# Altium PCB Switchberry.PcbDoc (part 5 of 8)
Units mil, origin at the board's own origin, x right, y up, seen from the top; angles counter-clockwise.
Board outline 4500 x 3824.8 mil, 6 copper layers (L01-TOP, L02-GND, L03-SIG, L04-SIG, L05-GND, L06-BOT), stack 49.214 mil thick; 431 components, 322 nets, 1699 pads, 1274 vias.
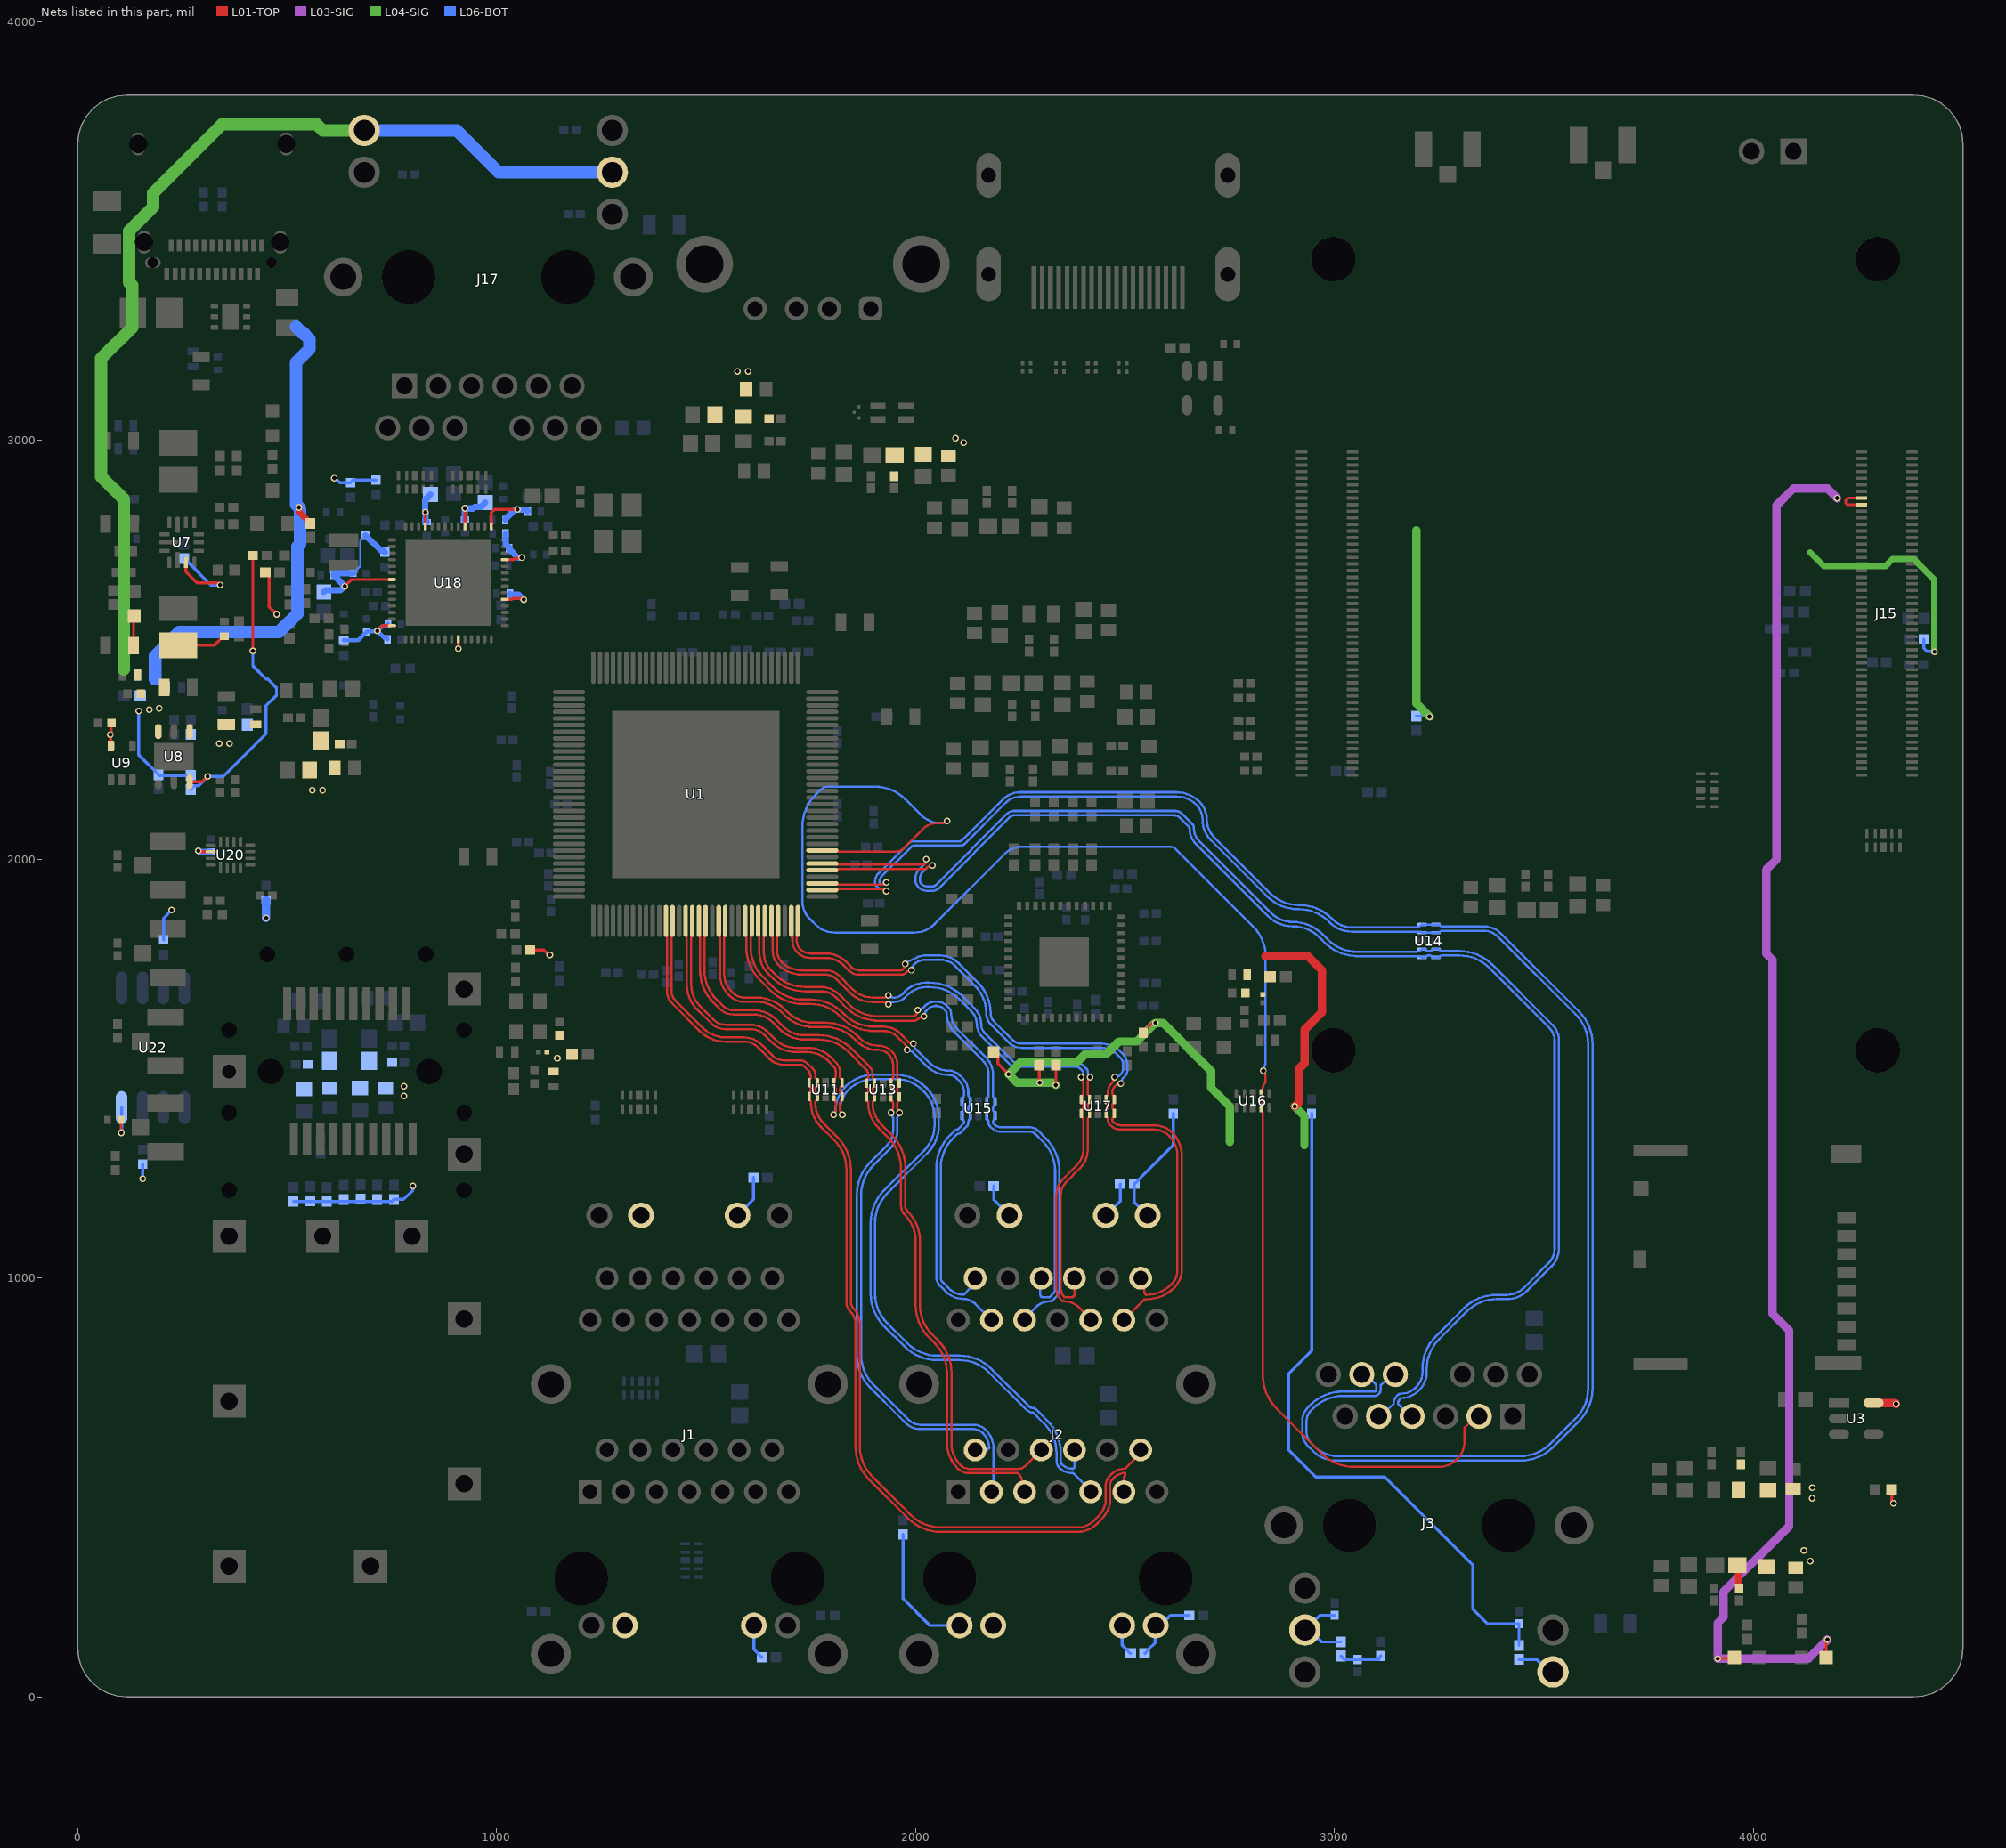
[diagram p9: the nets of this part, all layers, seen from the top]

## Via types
v1: diameter 16, hole 10, L01-TOP to L06-BOT, tented both sides, 1262 vias
v2: diameter 11.81, hole 7.87, L01-TOP to L06-BOT, tented both sides, 4 vias
v3: diameter 19.68, hole 7.87, L01-TOP to L06-BOT, tented both sides, 4 vias
v4: diameter 157.48, hole 110.24, L01-TOP to L06-BOT, tented both sides, 4 vias

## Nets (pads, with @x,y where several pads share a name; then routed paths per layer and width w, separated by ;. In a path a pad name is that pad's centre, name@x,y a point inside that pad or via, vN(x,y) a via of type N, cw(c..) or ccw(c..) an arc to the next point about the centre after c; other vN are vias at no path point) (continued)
P2_LED1: J2.34 R34.2 R98.1 | length 295.8
  L06-BOT w7.27: J2.34@2554,1150 2521.73,1182.27 R98.1@2521.73,1225 2522.72,1225 2530.89,1233.18 2530.89,1234.16 2615,1318.27 R34.2@2615,1393.27
P2_TXRXA_N: J2.13 U1.13 U11.2 U11.9 | length 2401.1
  L01-TOP w5.38: U1.13@1419.88,1852.82 1419.88,1820.14 cw(c1415.3,1820.14) 1418.54,1816.9 ccw(c1421.78,1813.66) 1417.2,1813.66 1417.2,1685 ccw(c1446.64,1685) 1425.82,1664.18 1493.79,1596.21 ccw(c1545,1647.43) 1545,1575 1589.84,1575 cw(c1589.84,1515.03) 1632.24,1557.44 1658.84,1530.84 ccw(c1685,1556.99) 1685,1520 1723.88,1520 cw(c1723.88,1493.93) 1742.31,1512.36 1754.84,1499.84 cw(c1741.66,1486.66) 1760.3,1486.66 1760.3,1482.19 ccw(c1768.86,1482.19) 1762.81,1476.13 cw(c1756.75,1470.07) 1765.31,1470.07 U11.9@1765.31,1466.44 1765.31,1460.13 cw(c1763.18,1460.13) 1764.69,1458.63 1764.07,1458 1763.81,1458 ccw(c1771.42,1450.4) 1760.66,1450.4 1760.66,1447.37 ccw(c1766.04,1447.37) 1762.24,1443.57 1763.81,1442 1764.07,1442 cw(c1761.05,1438.98) 1765.31,1438.98 U11.2@1765.31,1433.56 1765.31,1427.26 cw(c1763.18,1427.26) 1764.69,1425.75 1764.07,1425.13 1763.81,1425.13 ccw(c1771.42,1417.52) 1760.66,1417.52 ccw(c1828.71,1417.52) 1780.59,1369.41 1813.12,1336.88 cw(c1735.24,1259) 1845.38,1259 1845.38,942.75 ccw(c1866.09,942.75) 1851.45,928.1 cw(c1814.38,891.03) 1866.8,891.03 1866.8,597.99 ccw(c1966.8,597.99) 1896.09,527.28 1969.92,453.44 ; 1970,453.37 1989.08,434.29 ccw(c2059.79,505) 2059.79,405 2387.06,405 ccw(c2387.06,459.04) 2425.27,420.83 2436.23,431.8 ccw(c2393.48,474.55) 2453.94,474.55 2453.94,506.29 cw(c2483.71,506.29) 2462.66,527.34 2467.06,531.73 cw(c2500,498.79) 2500,545.38 2531.61,576.99 ccw(c2518.6,590) J2.13@2537,590
P2_TXRXA_P: J2.6 U1.12 U11.1 U11.10 | length 2403.6
  L01-TOP w5.38: U1.12@1404.13,1852.82 1404.13,1820.14 ccw(c1408.72,1820.14) 1405.48,1816.9 cw(c1402.24,1813.66) 1406.82,1813.66 1406.82,1684.97 ccw(c1446.58,1684.97) 1418.46,1656.86 1486.5,1588.82 ccw(c1544.92,1647.24) 1544.92,1564.62 1589.7,1564.62 cw(c1589.7,1514.7) 1625,1550 1651.52,1523.48 ccw(c1684.97,1556.93) 1684.97,1509.62 1723.84,1509.62 cw(c1723.84,1493.84) 1735,1505 1744.74,1495.26 cw(c1738.07,1488.59) 1747.5,1488.59 1747.5,1488.11 ccw(c1755.76,1488.11) 1749.92,1482.26 1749.92,1480.84 cw(c1742.6,1480.84) 1747.77,1475.66 ccw(c1752.95,1470.49) 1745.63,1470.49 U11.10@1745.63,1466.44 1745.63,1460.13 ccw(c1747.76,1460.13) 1746.25,1458.63 1746.88,1458 1747.13,1458 cw(c1739.53,1450.4) 1750.28,1450.4 1750.28,1447.37 cw(c1744.91,1447.37) 1748.71,1443.57 1747.13,1442 1746.88,1442 ccw(c1749.89,1438.98) 1745.63,1438.98 U11.1@1745.63,1433.56 1745.63,1427.26 ccw(c1747.76,1427.26) 1746.25,1425.75 1746.88,1425.13 1747.13,1425.13 cw(c1739.53,1417.52) 1750.28,1417.52 1750.28,1417.45 ccw(c1828.52,1417.45) 1773.2,1362.12 1805.71,1329.61 cw(c1735,1258.9) 1835,1258.9 1835,1129.96 1835,942.75 ccw(c1866.09,942.75) 1844.11,920.76 cw(c1814.38,891.03) 1856.42,891.03 1856.42,597.99 ccw(c1966.8,597.99) 1888.75,519.94 1981.74,426.95 ccw(c2059.79,505) 2059.79,394.62 2387.06,394.62 ccw(c2387.06,459.04) 2432.6,413.49 2443.57,424.46 ccw(c2393.48,474.55) 2464.32,474.55 2464.32,506.29 cw(c2483.71,506.29) 2470,520 2474.39,524.39 cw(c2500,498.79) 2500,535 2500,530.53 cw(c2494.88,530.53) 2498.5,526.91 ccw(c2502.12,523.29) 2497,523.29 J2.6@2497,490
P2_TXRXB_N: J2.5 U1.16 U11.5 U11.6 | length 2282.6
  L01-TOP w5.38: U1.16@1467.13,1852.82 1467.13,1820.14 cw(c1462.54,1820.14) 1465.78,1816.9 ccw(c1469.02,1813.66) 1464.44,1813.66 1464.44,1699.63 ccw(c1534.63,1699.63) 1484.97,1650.03 1519.44,1615.56 ccw(c1544.94,1641.07) 1544.94,1605 1604.84,1605 cw(c1604.84,1545.03) 1647.24,1587.44 1663.23,1571.44 ccw(c1715,1623.21) 1715,1550 1742.66,1550 cw(c1742.66,1472.72) 1797.31,1527.36 1810.19,1514.48 cw(c1787.2,1491.49) 1819.72,1491.49 1819.72,1480.25 ccw(c1825.09,1480.25) 1821.29,1476.45 1822.87,1474.87 1823.12,1474.87 cw(c1820.11,1471.86) U11.6@1824.37,1471.86 ; U11.6@1824.37,1466.44 1824.37,1460.13 cw(c1822.24,1460.13) 1823.75,1458.63 1823.12,1458 1822.87,1458 ccw(c1830.47,1450.4) 1819.72,1450.4 1819.72,1447.37 ccw(c1825.09,1447.37) 1821.29,1443.57 1822.87,1442 1823.12,1442 cw(c1820.11,1438.98) 1824.37,1438.98 U11.5@1824.37,1433.56 1824.37,1427.26 cw(c1822.24,1427.26) 1823.75,1425.75 1823.12,1425.13 1822.87,1425.13 ccw(c1830.47,1417.52) 1819.72,1417.52 1819.72,1401.94 ccw(c1828.78,1401.94) 1822.37,1395.53 1823,1394.91 cw(c1818.09,1390) v1(1825.03,1390)
  L06-BOT w5.38: v1(1825.03,1390) ccw(c1818.09,1390) 1823,1394.91 cw(c1830.91,1402.82) 1819.72,1402.82 cw(c1884.36,1402.82) 1838.65,1448.53 1840.12,1450 cw(c1900.47,1389.64) 1900.47,1475 1954.75,1475 1954.82,1475 cw(c1954.82,1390.07) 2014.93,1450.07 2020.36,1444.64 cw(c1960.62,1385.05) 2045,1385.48 cw(c1940.61,1385) 2045,1385 2045,1365.29 cw(c1959.97,1365.22) 2020.06,1305.06 1925.08,1210.08 ccw(c2003.13,1132.04) 1892.76,1132.04 1892.76,963.29 ccw(c2003.13,963.29) 1925.08,885.24 1973.37,836.95 ccw(c2051.42,915) 2051.42,804.62 2105,804.62 cw(c2105,707.14) 2173.93,776.07 2263.57,686.43 ccw(c2280,702.85) 2280,679.62 2306.89,652.73 cw(c2236.18,582.02) 2336.18,582.02 2336.18,563.3 ccw(c2358.3,563.3) 2342.66,547.66 ccw(c2374.14,579.14) 2374.14,534.62 cw(c2374.14,530.5) 2377.06,533.41 2416.25,494.22 cw(c2412.03,490) J2.5@2418,490
P2_TXRXB_P: J2.11 U1.15 U11.4 U11.7 | length 2287.8
  L01-TOP w5.38: U1.15@1451.38,1852.82 1451.38,1820.14 ccw(c1455.96,1820.14) 1452.72,1816.9 cw(c1449.48,1813.66) 1454.06,1813.66 1454.06,1699.59 ccw(c1534.52,1699.59) 1477.63,1642.69 1512.1,1608.23 ccw(c1544.94,1641.07) 1544.94,1594.62 1604.77,1594.62 ; 1604.81,1594.62 cw(c1604.84,1545.03) 1639.91,1580.09 1639.96,1580.04 1655.92,1564.08 ccw(c1714.97,1623.14) 1714.97,1539.62 1742.63,1539.62 cw(c1742.63,1446.36) 1742.85,1539.62 cw(c1742.66,1472.72) 1790.02,1519.98 1802.9,1507.1 cw(c1782.66,1486.98) 1802.97,1507.02 cw(c1787.2,1491.49) 1809.34,1491.49 1809.34,1484.44 1806.47,1468.22 1805.93,1467.69 U11.7@1804.68,1466.44 1804.68,1460.13 ccw(c1806.82,1460.13) 1805.31,1458.63 1805.93,1458 1806.19,1458 cw(c1798.58,1450.4) 1809.34,1450.4 1809.34,1447.37 cw(c1803.96,1447.37) 1807.76,1443.57 1806.19,1442 1805.93,1442 ccw(c1808.95,1438.98) 1804.68,1438.98 U11.4@1804.68,1433.56 1804.68,1427.26 ccw(c1806.82,1427.26) 1805.31,1425.75 1805.93,1425.13 1806.19,1425.13 cw(c1798.58,1417.52) 1809.34,1417.52 1809.34,1401.94 cw(c1800.27,1401.94) 1806.68,1395.53 1806.06,1394.91 ccw(c1810.97,1390) v1(1804.03,1390)
  L06-BOT w5.38: v1(1804.03,1390) cw(c1810.97,1390) 1806.06,1394.91 ccw(c1798.14,1402.82) 1809.34,1402.82 ; 1809.34,1402.87 cw(c1884.25,1402.87) 1831.28,1455.84 1832.8,1457.36 cw(c1900.45,1389.71) 1900.45,1485.38 1954.82,1485.38 cw(c1954.82,1390.07) 2022.21,1457.46 2027.63,1452.05 cw(c1960.62,1385.05) 2055.38,1385.05 2055.38,1365.22 cw(c1959.97,1365.22) 2027.43,1297.76 1932.42,1202.75 ccw(c2003.13,1132.04) 1903.13,1132.04 1903.13,963.29 ccw(c2003.13,963.29) 1932.42,892.58 1980.71,844.29 ccw(c2051.42,915) 2051.42,815 2105,815 cw(c2105,707.14) 2181.27,783.41 2270.91,693.76 ccw(c2280,702.85) 2280,690 cw(c2280,679.62) 2287.34,686.96 2314.23,660.07 cw(c2236.18,582.02) 2346.56,582.02 2346.56,563.3 ccw(c2358.3,563.3) 2350,555 ccw(c2374.14,579.14) 2374.14,545 ccw(c2374.14,549.12) 2377.06,546.21 ccw(c2372.37,550.9) 2379,550.9 J2.11@2379,590
P2_TXRXC_N: J2.10 U1.18 U13.2 U13.9 | length 1849
  L01-TOP w5.38: U1.18@1498.62,1852.82 1498.62,1820.14 cw(c1494.04,1820.14) 1497.28,1816.9 ccw(c1500.52,1813.66) 1495.94,1813.66 1495.94,1735.16 ccw(c1595.16,1735.16) 1525,1665 1539.39,1650.61 ccw(c1565,1676.21) 1565,1640 1612.66,1640 cw(c1612.66,1562.72) 1667.31,1617.36 1683.23,1601.44 ccw(c1735,1653.21) 1735,1580 1769.06,1580 cw(c1769.06,1469.86) 1846.93,1547.74 1890.58,1504.1 cw(c1873.86,1487.38) 1897.51,1487.38 1897.51,1479.81 ccw(c1902.88,1479.81) 1899.08,1476.01 1900.66,1474.43 1900.91,1474.43 cw(c1897.9,1471.42) 1902.16,1471.42 U13.9@1902.16,1466 1902.16,1459.7 cw(c1900.03,1459.7) 1901.54,1458.19 1900.91,1457.57 1900.66,1457.57 ccw(c1908.26,1449.96) 1897.51,1449.96 1897.51,1446.94 ccw(c1902.88,1446.94) 1899.08,1443.13 1900.66,1441.56 1900.91,1441.56 cw(c1897.9,1438.55) 1902.16,1438.55 U13.2@1902.16,1433.13 1902.16,1426.82 cw(c1900.03,1426.82) 1901.54,1425.32 1900.91,1424.69 1900.66,1424.69 ccw(c1908.26,1417.09) 1897.51,1417.09 ccw(c1968.95,1417.09) 1918.43,1366.57 1943.12,1341.88 cw(c1865.24,1264) 1975.38,1264 1975.38,1173.58 ccw(c1997.01,1173.58) 1981.71,1158.29 cw(c1912.51,1089.08) 2010.38,1089.08 2010.38,936.04 ccw(c2110.38,936.04) 2039.67,865.33 2053.05,851.95 cw(c1975,773.9) 2085.38,773.9 2085.38,606.37 ccw(c2160.34,606.37) 2107.33,553.36 ccw(c2127.92,573.94) 2127.92,544.84 2245,544.84 ccw(c2245,568.58) 2261.79,551.79 J2.10@2300,590
P2_TXRXC_P: J2.3 U1.17 U13.1 U13.10 | length 1840.9
  L01-TOP w5.38: U1.17@1482.87,1852.82 1482.87,1820.14 ccw(c1487.46,1820.14) 1484.22,1816.9 cw(c1480.98,1813.66) 1485.56,1813.66 1485.56,1735.1 ccw(c1595.01,1735.1) 1517.62,1657.71 1532.1,1643.23 ccw(c1564.94,1676.07) 1564.94,1629.62 1612.63,1629.62 cw(c1612.63,1562.63) 1660,1610 1675.92,1594.08 ccw(c1734.97,1653.14) 1734.97,1569.62 1768.96,1569.62 cw(c1768.96,1469.62) 1839.67,1540.33 1881.72,1498.28 cw(c1868.67,1485.23) 1887.13,1485.23 1887.13,1479.81 cw(c1881.75,1479.81) 1885.55,1476.01 1883.98,1474.43 1883.72,1474.43 ccw(c1886.74,1471.42) 1882.47,1471.42 U13.10@1882.47,1466 1882.47,1459.7 ccw(c1884.6,1459.7) 1883.1,1458.19 1883.72,1457.57 1883.98,1457.57 cw(c1876.37,1449.96) 1887.13,1449.96 1887.13,1446.94 cw(c1881.75,1446.94) 1885.55,1443.13 1883.98,1441.56 1883.72,1441.56 ccw(c1886.74,1438.55) 1882.47,1438.55 U13.1@1882.47,1433.13 1882.47,1426.82 ccw(c1884.6,1426.82) 1883.1,1425.32 1883.72,1424.69 1883.98,1424.69 cw(c1876.37,1417.09) 1887.13,1417.09 ; 1887.13,1417.04 ccw(c1968.84,1417.04) 1911.06,1359.26 1935.71,1334.61 cw(c1865,1263.9) 1965,1263.9 1965,1173.58 ccw(c1997.01,1173.58) 1974.37,1150.95 cw(c1912.51,1089.08) 2000,1089.08 2000,936.04 ccw(c2110.38,936.04) 2032.33,857.99 2045.71,844.61 cw(c1975,773.9) 2075,773.9 2075,606.37 ccw(c2160.34,606.37) 2100,546.02 ccw(c2127.92,573.94) 2127.92,534.46 2245,534.46 cw(c2223.15,512.61) 2254.05,512.61 2254.05,504.37 ccw(c2274.37,504.37) J2.3@2260,490
P2_TXRXD_N: J2.2 U1.21 U13.5 U13.6 | length 1905.5
  L01-TOP w5.38: U1.21@1545.87,1852.82 1545.87,1820.14 cw(c1541.28,1820.14) 1544.52,1816.9 ccw(c1547.76,1813.66) 1543.18,1813.66 1543.18,1725.84 ccw(c1600.6,1725.84) 1560,1685.23 1564.79,1680.44 ccw(c1590,1705.65) 1590,1670 1620.59,1670 cw(c1620.59,1575.65) 1687.31,1642.36 1694.7,1634.98 ccw(c1755,1695.28) 1755,1610 1784.06,1610 cw(c1784.06,1499.86) 1861.93,1577.74 1866.13,1573.55 ccw(c1910,1617.43) 1866.18,1573.5 ccw(c1910,1617.43) 1910,1555.38 1910.98,1555.38 cw(c1910.98,1511.15) 1942.25,1542.42 1942.42,1542.25 cw(c1908.29,1508.12) 1956.56,1508.12 1956.56,1479.81 ccw(c1961.94,1479.81) 1958.14,1476.01 1959.71,1474.43 1959.97,1474.43 cw(c1956.95,1471.42) 1961.21,1471.42 U13.6@1961.21,1466 1961.21,1459.7 cw(c1959.08,1459.7) 1960.59,1458.19 1959.97,1457.57 1959.71,1457.57 ccw(c1967.32,1449.96) 1956.56,1449.96 1956.56,1446.94 ccw(c1961.94,1446.94) 1958.14,1443.13 1959.71,1441.56 1959.97,1441.56 cw(c1956.95,1438.55) 1961.21,1438.55 U13.5@1961.21,1433.13 1961.21,1426.82 cw(c1959.08,1426.82) 1960.59,1425.32 1959.97,1424.69 1959.71,1424.69 ccw(c1967.32,1417.09) 1956.56,1417.09 1956.56,1406.94 ccw(c1965.63,1406.94) 1959.22,1400.53 1959.84,1399.91 cw(c1954.93,1395) v1(1961.87,1395)
  L06-BOT w5.38: v1(1961.87,1395) cw(c1954.93,1395) 1959.84,1390.09 ccw(c1967.75,1382.18) 1956.56,1382.18 1956.56,1353.96 cw(c1891.18,1353.96) 1937.41,1307.74 1899.29,1269.61 ccw(c1970,1198.9) 1870,1198.9 1870,816.42 ccw(c1970,816.42) 1899.29,745.71 1982.5,662.5 ccw(c2012.68,692.68) 2012.68,650 2138.64,650 cw(c2138.64,610.39) 2166.65,638.4 2168.4,636.65 cw(c2125.79,594.04) 2186.05,594.04 cw(c2175.67,594.04) 2186.04,593.81 2185.98,590.77 ccw(c2221,590) 2186.04,587.84 cw(c2180.67,587.49) 2186.05,587.49 2186.05,502.18 cw(c2168.82,502.18) J2.2@2181,490
P2_TXRXD_P: J2.8 U1.20 U13.4 U13.7 | length 1834.9
  L01-TOP w5.38: U1.20@1530.12,1852.82 1530.12,1820.14 ccw(c1534.7,1820.14) 1531.46,1816.9 cw(c1528.22,1813.66) 1532.8,1813.66 1532.8,1725.79 ccw(c1600.49,1725.79) 1552.63,1677.93 1557.51,1673.05 ccw(c1589.92,1705.47) 1589.92,1659.62 1620.56,1659.62 cw(c1620.56,1575.56) 1680,1635 1687.38,1627.62 ccw(c1754.97,1695.21) 1754.97,1599.62 1783.96,1599.62 cw(c1783.96,1499.62) 1854.62,1570.38 1861.83,1563.17 1865.21,1560.51 ccw(c1910,1617.43) 1901.43,1545.51 1905.7,1545 1910.86,1545 ; 1910.9,1545 cw(c1910.86,1510.86) 1935,1535 cw(c1908,1508) 1946.18,1508 1946.18,1479.81 cw(c1940.8,1479.81) 1944.61,1476.01 1943.03,1474.43 1942.78,1474.43 ccw(c1945.79,1471.42) 1941.53,1471.42 U13.7@1941.53,1466 1941.53,1459.7 ccw(c1943.66,1459.7) 1942.15,1458.19 1942.78,1457.57 1943.03,1457.57 cw(c1935.43,1449.96) 1946.18,1449.96 1946.18,1446.94 cw(c1940.8,1446.94) 1944.61,1443.13 1943.03,1441.56 1942.78,1441.56 ccw(c1945.79,1438.55) 1941.53,1438.55 U13.4@1941.53,1433.13 1941.53,1426.82 ccw(c1943.66,1426.82) 1942.15,1425.32 1942.78,1424.69 1943.03,1424.69 cw(c1935.43,1417.09) 1946.18,1417.09 1946.18,1406.94 cw(c1937.12,1406.94) 1943.53,1400.53 1942.9,1399.91 ccw(c1947.81,1395) v1(1940.87,1395)
  L06-BOT w5.38: v1(1940.87,1395) ccw(c1947.81,1395) 1942.9,1390.09 cw(c1934.99,1382.18) 1946.18,1382.18 1946.18,1354.07 cw(c1890.93,1354.07) 1930,1315 1891.92,1276.92 ccw(c1969.89,1198.95) 1859.62,1198.95 1859.62,816.42 ccw(c1970,816.42) 1891.95,738.37 1962.66,667.66 1975.16,655.16 ccw(c2012.68,692.68) 2012.68,639.62 2138.64,639.62 cw(c2138.64,610.39) 2159.31,631.06 2161.06,629.31 cw(c2125.79,594.04) 2175.67,594.04 cw(c2168.06,601.65) 2168.06,590.89 2144.15,590.89 ccw(c2144.15,587.85) J2.8@2142,590
P2V5: C56.1 C57.1 C58.1 C59.2 C106.1 C107.2 C108.1 C149.1 C150.2 C151.1 FB8.1 FB10.1 R72.2 U8.4
  other v1: 560,2165 585,2165 337.84,2276.55 362.84,2276.55 2115,2995 2095,3005
P2V5_PGOOD: R71.1 R79.2 U8.3 | length 745
  L01-TOP w7.27: U8.3@267.4,2184.96 296.76,2184.96 309.54,2197.75 v1(310.71,2197.75) ; v1(418.27,2497.12) R79.2@418.27,2725
  L06-BOT w7.27: R71.1@270,2166.54 270,2167.52 278.18,2175.7 288.66,2175.7 v1(310.71,2197.75) 347.75,2197.75 450,2300 450,2366.42 474.57,2390.98 474.57,2408.96 453.53,2430 450,2430 418.27,2461.73 v1(418.27,2497.12)
P3_LED0: J2.27 R35.2 | length 314.8
  L06-BOT w7.27: R35.2@1970,388.27 1970,235 2034,171 J2.27@2105,171
P3_LED1: J2.30 R36.2 R102.1 | length 167.7
  L06-BOT w7.27: R102.1@2546.73,105 2547.72,105 2555.89,113.18 2555.89,114.16 2571,129.27 2571,169 J2.30@2573,171 2584.02,171 2608.02,195 R36.2@2653.27,195
P3_TXRXA_N: J2.21 U1.25 U15.2 U15.9 | length 1334.2
  L01-TOP w5.38: U1.25@1608.86,1852.82 1608.86,1820.14 cw(c1604.27,1820.14) 1607.52,1816.9 ccw(c1610.76,1813.66) 1606.17,1813.66 1606.17,1790.25 ccw(c1706.17,1790.25) 1635.46,1719.54 1660.71,1694.29 ccw(c1731.42,1765) 1731.42,1665 1750.03,1665 cw(c1750.03,1557.21) 1826.25,1633.43 1830.01,1629.67 ccw(c1900.72,1700.38) 1900.72,1600.38 1923.96,1600.38 cw(c1923.96,1545.2) 1962.97,1584.22 1982.65,1564.54 ccw(c1989.06,1570.95) 1989.06,1561.88 1989.94,1561.88 cw(c1989.94,1554.94) v1(1994.85,1559.85)
  L06-BOT w5.38: v1(1994.85,1559.85) cw(c1989.94,1554.94) 1996.88,1554.94 1996.88,1554.06 ccw(c2005.95,1554.06) 1999.54,1547.65 2031.88,1515.31 ; 2031.89,1515.3 ccw(c2080,1563.44) 2080,1495.38 cw(c2080.03,1460.93) 2104.39,1485.29 2112.37,1477.31 cw(c2080.29,1445.22) 2125.66,1445.22 2125.66,1437.48 ccw(c2136.42,1437.48) 2128.81,1429.87 2129.07,1429.87 2129.69,1429.25 cw(c2128.18,1427.74) 2130.31,1427.74 U15.2@2130.31,1421.44 2130.31,1415.13 cw(c2128.18,1415.13) 2129.69,1413.63 2129.07,1413 2128.81,1413 ccw(c2136.42,1405.4) 2125.66,1405.4 2125.66,1402.37 ccw(c2131.04,1402.37) 2127.24,1398.57 2128.81,1397 2129.07,1397 cw(c2126.05,1393.98) 2130.31,1393.98 U15.9@2130.31,1388.56 2130.31,1382.26 cw(c2128.18,1382.26) 2129.69,1380.75 2129.07,1380.13 2128.81,1380.13 ccw(c2136.42,1372.52) 2125.66,1372.52 2125.66,1369.99 cw(c2115.31,1369.99) 2122.63,1362.67 2107.59,1347.63 cw(c2100.32,1354.9) 2100.32,1344.62 2100,1344.62 2089.29,1333.91 ccw(c2160,1263.2) 2060,1263.2 2060,1002.07 ccw(c2077.07,1002.07) 2065,990 2079.62,975.38 ccw(c2114.84,1010.61) 2114.84,960.79 2133.48,979.43 ccw(c2112.9,1000) J2.21@2142,1000
P3_TXRXA_P: J2.15 U1.24 U15.1 U15.10 | length 1386.7
  L01-TOP w5.38: U1.24@1593.11,1852.82 1593.11,1820.14 ccw(c1597.69,1820.14) 1594.45,1816.9 cw(c1591.21,1813.66) 1595.8,1813.66 1595.8,1790.22 ccw(c1706.11,1790.22) 1628.11,1712.22 1653.39,1686.93 ccw(c1731.39,1764.93) 1731.39,1654.62 1750,1654.62 cw(c1750,1557.14) 1818.93,1626.07 1822.69,1622.31 ccw(c1900.69,1700.31) 1900.69,1590 1923.87,1590 cw(c1923.87,1544.99) 1955.69,1576.82 1975.31,1557.2 cw(c1968.9,1550.79) 1977.97,1550.79 1977.97,1549.91 ccw(c1984.91,1549.91) v1(1980,1545)
  L06-BOT w5.38: v1(1980,1545) ccw(c1984.91,1549.91) 1984.91,1542.97 1985.79,1542.97 cw(c1985.79,1533.9) 1992.2,1540.31 2024.54,1507.97 ; 2024.56,1507.95 ccw(c2080,1563.44) 2080,1485 cw(c2080,1460.86) 2097.07,1477.93 2105,1470 cw(c2080.17,1445.17) 2115.28,1445.17 2115.28,1437.48 cw(c2104.53,1437.48) 2112.13,1429.87 2111.88,1429.87 2111.25,1429.25 ccw(c2112.76,1427.74) 2110.63,1427.74 U15.1@2110.63,1421.44 2110.63,1415.13 ccw(c2112.76,1415.13) 2111.25,1413.63 2111.88,1413 2112.13,1413 cw(c2104.53,1405.4) 2115.28,1405.4 2115.28,1402.37 cw(c2109.91,1402.37) 2113.71,1398.57 2112.13,1397 2111.88,1397 ccw(c2114.89,1393.98) 2110.63,1393.98 U15.10@2110.63,1388.56 2110.63,1382.26 ccw(c2112.76,1382.26) 2111.25,1380.75 2111.88,1380.13 2112.13,1380.13 cw(c2104.53,1372.52) 2115.28,1372.52 2115.28,1370 2100.28,1355 2099.99,1355 ccw(c2099.99,1344.65) 2092.67,1351.97 2081.92,1341.22 ccw(c2159.89,1263.25) 2049.62,1263.25 2049.62,1002.07 ccw(c2077.07,1002.07) 2057.66,982.66 2072.28,968.04 ccw(c2114.84,1010.61) 2114.84,950.41 cw(c2114.84,912.41) 2141.72,939.28 J2.15@2181,900
P3_TXRXB_N: J2.16 U1.27 U15.5 U15.6 | length 1548.2
  L01-TOP w5.38: U1.27@1640.35,1852.82 1640.35,1820.14 cw(c1635.77,1820.14) 1639.01,1816.9 ccw(c1642.25,1813.66) 1637.67,1813.66 1637.67,1776.84 ccw(c1696.84,1776.84) 1655,1735 1665.43,1724.57 ccw(c1736.14,1795.28) 1736.14,1695.28 1774.06,1695.28 cw(c1774.06,1634.12) 1817.31,1677.36 1840.39,1654.29 ccw(c1911.1,1725) 1911.1,1625 1993.65,1625 ccw(c1993.65,1634.32) 2000.24,1627.73 2000.31,1627.8 ccw(c1993.9,1634.21) 2002.97,1634.21 2002.97,1635.09 cw(c2009.91,1635.09) v1(2005,1640)
  L06-BOT w5.38: v1(2005,1640) cw(c2009.91,1635.09) 2009.91,1642.03 2010.79,1642.03 ccw(c2010.79,1651.1) 2017.2,1644.69 2023.72,1651.21 cw(c2036.82,1638.1) 2027.62,1654.19 2028.86,1654.95 cw(c2048.01,1623.87) 2039.6,1659.4 2043.71,1660.38 2052.89,1660.38 2056.98,1659.44 cw(c2048.59,1622.46) 2068.78,1654.56 2072.36,1652.31 2081.2,1643.48 2082.92,1639.64 cw(c2061.64,1630) 2083.51,1638.21 2084.99,1634.32 ; 2085,1634.3 2085,1630 ccw(c2134.06,1630) 2099.37,1595.31 2167.14,1527.54 cw(c2124.7,1485.1) 2184.72,1485.1 2184.72,1433.02 2187.87,1429.87 2188.12,1429.87 2189.37,1428.62 U15.5@2189.37,1421.44 2189.37,1415.13 cw(c2187.24,1415.13) 2188.75,1413.63 2188.12,1413 2187.87,1413 ccw(c2195.47,1405.4) 2184.72,1405.4 2184.72,1402.37 ccw(c2190.09,1402.37) 2186.29,1398.57 2187.87,1397 2188.12,1397 cw(c2185.11,1393.98) 2189.37,1393.98 U15.6@2189.37,1388.56 2189.37,1382.26 cw(c2187.24,1382.26) 2188.75,1380.75 2188.12,1380.13 2187.87,1380.13 ccw(c2195.47,1372.52) 2184.72,1372.52 2184.72,1370 2187.45,1367.27 ccw(c2205,1384.83) 2205,1360 2273.88,1360 cw(c2273.88,1333.93) 2292.31,1352.36 2310.97,1333.71 cw(c2233.09,1255.83) 2343.23,1255.83 2343.23,975 cw(c2315.59,975) 2335.13,955.46 2327.34,947.66 cw(c2320,955) 2320,944.62 ccw(c2320,898.16) 2287.15,931.01 2262.73,906.6 ccw(c2269.33,900) J2.16@2260,900
P3_TXRXB_P: J2.23 U1.26 U15.4 U15.7 | length 1519.2
  L01-TOP w5.38: U1.26@1624.61,1852.82 1624.61,1820.14 ccw(c1629.19,1820.14) 1625.95,1816.9 cw(c1622.71,1813.66) 1627.29,1813.66 1627.29,1776.79 ccw(c1696.73,1776.79) 1647.63,1727.69 1658.11,1717.21 ccw(c1736.12,1795.21) 1736.12,1684.9 1774.03,1684.9 cw(c1774.03,1634.03) 1810,1670 1836.09,1643.91 1839.36,1641.12 ccw(c1911.1,1725) 1902.51,1614.96 1906.8,1614.62 1995.8,1614.62 ccw(c1995.8,1629.13) 2006.06,1618.87 2007.65,1620.46 cw(c2014.06,1614.05) 2014.06,1623.12 2014.94,1623.12 ccw(c2014.94,1630.06) v1(2019.85,1625.15)
  L06-BOT w5.38: v1(2019.85,1625.15) ccw(c2014.94,1630.06) 2021.88,1630.06 2021.88,1630.94 cw(c2030.95,1630.94) 2024.54,1637.35 2029.53,1642.35 cw(c2048.01,1623.87) 2048.01,1650 2048.59,1650 cw(c2048.59,1622.46) 2068.07,1641.93 2070.82,1639.18 cw(c2061.64,1630) 2074.62,1630 ccw(c2134,1629.97) 2092.01,1587.99 2159.73,1520.27 cw(c2124.46,1485) 2174.34,1485 2174.34,1433.02 2171.19,1429.87 2170.93,1429.87 2169.68,1428.62 U15.4@2169.68,1421.44 2169.68,1415.13 ccw(c2171.82,1415.13) 2170.31,1413.63 2170.93,1413 2171.19,1413 cw(c2163.58,1405.4) 2174.34,1405.4 2174.34,1402.37 cw(c2168.96,1402.37) 2172.76,1398.57 2171.19,1397 2170.93,1397 ccw(c2173.95,1393.98) 2169.68,1393.98 U15.7@2169.68,1388.56 2169.68,1382.26 ccw(c2171.82,1382.26) 2170.31,1380.75 2170.93,1380.13 2171.19,1380.13 cw(c2163.58,1372.52) 2174.34,1372.52 2174.34,1369.99 ccw(c2184.69,1369.99) 2177.37,1362.67 2180.15,1359.89 ccw(c2204.94,1384.68) 2204.94,1349.62 2273.84,1349.62 cw(c2273.84,1333.84) 2285,1345 2303.56,1326.44 cw(c2232.85,1255.73) 2332.85,1255.73 2332.85,975 cw(c2315.59,975) 2327.79,962.79 2320,955 2302.98,955 cw(c2302.98,960.38) 2299.18,956.58 cw(c2302.98,960.38) 2297.61,960.38 2297.61,994.22 cw(c2305.78,994.22) J2.23@2300,1000
P3_TXRXC_N: J2.24 U1.29 U17.2 U17.9 | length 1612.5
  L01-TOP w5.38: U1.29@1671.85,1852.82 1671.85,1820.14 cw(c1667.27,1820.14) 1670.51,1816.9 ccw(c1673.75,1813.66) 1669.17,1813.66 1669.17,1781.16 ccw(c1706.16,1781.16) 1680,1755 ccw(c1728.28,1803.28) 1728.28,1735 1786.81,1735 cw(c1786.81,1691.86) 1817.31,1722.36 1849.9,1689.78 ccw(c1898.4,1738.29) 1898.4,1669.69 1923.06,1669.69 ccw(c1923.06,1678.76) 1929.47,1672.34 1930.09,1672.97 cw(c1935,1668.06) v1(1935,1675) ; J2.24@2379,1000 2379,960.38 cw(c2373.62,960.38) 2377.42,956.58 cw(c2373.62,960.38) 2373.62,955 2355,955 cw(c2375.8,975.8) 2346.39,975.8 2346.39,1197.13 cw(c2392.87,1197.13) 2360,1230 2375.64,1245.64 2375.64,1245.96 2392.41,1262.74 ccw(c2348.36,1306.79) 2410.66,1306.79 2410.66,1377.52 cw(c2421.42,1377.52) 2413.81,1385.13 2414.07,1385.13 2414.69,1385.75 ccw(c2413.18,1387.26) 2415.31,1387.26 U17.2@2415.31,1393.56 2415.31,1400.75 2414.07,1402 2413.81,1402 2410.66,1405.15 2410.66,1414.85 2413.81,1418 2414.07,1418 2415.31,1419.25 U17.9@2415.31,1426.44 2415.31,1432.74 ccw(c2413.18,1432.74) 2414.69,1434.25 2414.07,1434.87 2413.81,1434.87 cw(c2421.42,1442.48) 2410.66,1442.48 2410.66,1468.06 cw(c2419.73,1468.06) 2413.32,1474.47 2413.94,1475.09 ccw(c2409.03,1480) v1(2415.97,1480)
  L06-BOT w5.38: v1(1935,1675) cw(c1935,1668.06) 1939.91,1672.97 ccw(c1947.82,1680.88) 1947.82,1669.69 ccw(c1947.82,1698.34) 1968.08,1678.08 1975,1685 cw(c2024.2,1635.8) 2024.2,1705.38 2033.68,1705.38 cw(c2033.68,1595.24) 2111.56,1673.12 2140.55,1644.13 cw(c2101.51,1605.09) 2156.72,1605.09 2156.72,1605 ccw(c2185,1605) 2165,1585 2231.65,1518.35 ccw(c2239.73,1526.43) 2239.73,1515 2380.34,1515 cw(c2380.34,1484.73) 2401.74,1506.13 2407.47,1500.41 ; 2407.48,1500.4 cw(c2399.76,1492.7) 2410.66,1492.7 2410.66,1491.94 ccw(c2419.73,1491.94) 2413.32,1485.53 2413.94,1484.91 cw(c2409.03,1480) v1(2415.97,1480)
P3_TXRXC_P: J2.18 U1.28 U17.1 U17.10 | length 1642.8
  L01-TOP w5.38: U1.28@1656.1,1852.82 1656.1,1820.14 ccw(c1660.69,1820.14) 1657.44,1816.9 cw(c1654.2,1813.66) 1658.79,1813.66 1658.79,1781.11 ccw(c1706.04,1781.11) 1672.63,1747.69 ; 1672.66,1747.66 ccw(c1728.28,1803.28) 1728.28,1724.62 1786.77,1724.62 cw(c1786.77,1691.77) 1810,1715 1844.08,1680.92 ccw(c1896.25,1733.1) 1896.25,1659.31 1923.06,1659.31 cw(c1923.06,1650.24) 1929.47,1656.66 1930.09,1656.03 ccw(c1935,1660.94) v1(1935,1654) ; v1(2394.97,1480) ccw(c2401.91,1480) 2397,1475.1 2397.63,1474.47 cw(c2391.22,1468.06) 2400.28,1468.06 2400.28,1442.48 cw(c2389.53,1442.48) 2397.13,1434.87 2396.88,1434.87 2396.25,1434.25 ccw(c2397.76,1432.74) 2395.63,1432.74 U17.10@2395.63,1426.44 2395.63,1419.25 2396.88,1418 2397.13,1418 2400.28,1414.85 2400.28,1405.15 2397.13,1402 2396.88,1402 2395.63,1400.75 U17.1@2395.63,1393.56 2395.63,1387.26 ccw(c2397.76,1387.26) 2396.25,1385.75 2396.88,1385.13 2397.13,1385.13 cw(c2389.53,1377.52) 2400.28,1377.52 2400.28,1306.86 ; 2400.28,1306.82 cw(c2348.36,1306.79) 2385.09,1270.09 2385,1270 2365.26,1250.26 2365.26,1249.94 2352.66,1237.34 ccw(c2392.87,1197.13) 2336.01,1197.13 2336.01,975.8 ccw(c2375.8,975.8) 2347.66,947.66 ccw(c2355,955) 2355,944.62 cw(c2355,894.29) 2390.59,929.88 2416.25,904.22 cw(c2412.03,900) J2.18@2418,900
  L06-BOT w5.38: v1(1935,1654) ccw(c1935,1660.94) 1939.91,1656.03 cw(c1947.82,1648.12) 1947.82,1659.31 1947.91,1659.31 ccw(c1947.91,1698.14) 1975.36,1670.68 1981.77,1677.09 cw(c2025,1633.86) 2025,1695 2033.58,1695 cw(c2033.58,1595) 2104.29,1665.71 2133.12,1636.88 cw(c2101.51,1605.09) 2146.34,1605.09 2146.34,1600.7 ; 2146.34,1600.7 2147.28,1596.53 ccw(c2185,1605) 2152.33,1584.33 2154.62,1580.7 2217.06,1518.27 2224.27,1511.05 ; 2224.3,1511.03 ccw(c2239.73,1526.43) 2224.33,1510.99 ccw(c2239.73,1526.43) 2239.73,1504.62 2380.3,1504.62 cw(c2380.3,1484.64) 2394.43,1498.77 2398.61,1494.59 cw(c2394.57,1490.55) 2400.28,1490.55 cw(c2394.57,1490.55) 2398.61,1486.51 2397,1484.91 ccw(c2401.91,1480) v1(2394.97,1480)
P3_TXRXD_N: J2.19 U1.32 U17.5 U17.6 | length 1851.9
  L01-TOP w5.38: U1.32@1719.09,1852.82 1719.09,1820.14 cw(c1714.51,1820.14) 1717.75,1816.9 ccw(c1720.99,1813.66) 1716.41,1813.66 1716.41,1805.74 1716.41,1805.57 ccw(c1750.54,1805.74) 1716.41,1805.42 ccw(c1745.65,1805.7) 1724.99,1785.01 ccw(c1749.06,1808.94) 1749.06,1775 1786.62,1775 cw(c1786.62,1707.27) 1834.52,1755.16 1847.34,1742.34 ccw(c1865.05,1760.06) 1865.05,1735 1963.65,1735 ccw(c1963.65,1744.32) 1970.24,1737.73 1970.31,1737.8 ccw(c1963.9,1744.21) 1972.97,1744.21 1972.97,1745.09 cw(c1979.91,1745.09) v1(1975,1750) ; v1(2490,1465) cw(c2485.09,1469.91) 2485.09,1462.97 2484.21,1462.97 ccw(c2484.21,1453.9) 2477.8,1460.31 2475.09,1457.6 ccw(c2488.05,1444.63) 2469.72,1444.63 2469.72,1442.48 ccw(c2480.47,1442.48) 2472.87,1434.87 2473.12,1434.87 2473.75,1434.25 cw(c2472.24,1432.74) 2474.37,1432.74 U17.6@2474.37,1426.44 2474.37,1421.02 cw(c2470.11,1421.02) 2473.12,1418 2472.87,1418 2471.29,1416.43 ccw(c2475.09,1412.63) 2469.72,1412.63 2469.72,1409.6 ccw(c2480.47,1409.6) 2472.87,1402 2473.12,1402 2473.75,1401.37 cw(c2472.24,1399.87) 2474.37,1399.87 U17.5@2474.37,1393.56 2474.37,1387.26 cw(c2472.24,1387.26) 2473.75,1385.75 2473.12,1385.13 2472.87,1385.13 ccw(c2480.47,1377.52) 2469.72,1377.52 2469.72,1375 2472.45,1372.27 ccw(c2490,1389.83) 2490,1365 2569.84,1365 cw(c2569.84,1305.03) 2612.24,1347.44 2612.44,1347.24 cw(c2557.07,1291.86) 2635.38,1291.86 2635.38,1021.21 cw(c2573.79,1021.21) 2617.34,977.66 2617.09,977.41 cw(c2550,1044.5) 2550,949.62 ccw(c2550,941.47) 2544.23,947.23 J2.19@2497,900
  L06-BOT w5.38: v1(1975,1750) cw(c2005.2,1719.8) 1992.91,1760.7 2000.72,1764.71 cw(c2024.2,1718.94) 2015.66,1769.66 2019.9,1770.38 2058.83,1770.38 cw(c2058.83,1708.9) 2102.31,1752.37 2148.3,1706.38 cw(c2074.03,1632.11) 2179.06,1632.11 2179.06,1631.94 ccw(c2205.62,1631.94) 2186.84,1613.16 2229.9,1570.1 2229.98,1570.02 ccw(c2254.14,1594.14) 2254.14,1560 2444.84,1560 cw(c2444.84,1500.03) 2487.24,1542.44 2495.34,1534.34 cw(c2471.09,1510.1) 2505.38,1510.1 2505.38,1497.33 cw(c2482.6,1497.33) 2498.71,1481.22 2494.69,1477.2 ccw(c2501.1,1470.79) 2492.03,1470.79 2492.03,1469.91 cw(c2485.09,1469.91) v1(2490,1465)
P3_TXRXD_P: J2.26 U1.31 U17.4 U17.7 | length 1806.6
  L01-TOP w5.38: U1.31@1703.35,1852.82 1703.35,1820.14 ccw(c1707.93,1820.14) 1704.69,1816.9 cw(c1701.45,1813.66) 1706.03,1813.66 1706.03,1805.7 ccw(c1745.65,1805.7) 1717.64,1777.69 1717.72,1777.6 ccw(c1749.06,1808.94) 1749.06,1764.62 1786.62,1764.62 cw(c1786.62,1707.27) 1827.24,1747.76 1840.01,1734.99 ccw(c1865.04,1760.03) 1865.04,1724.62 1965.8,1724.62 ccw(c1965.8,1739.13) 1976.06,1728.87 1977.65,1730.46 cw(c1984.06,1724.05) 1984.06,1733.12 1984.94,1733.12 ccw(c1984.94,1740.06) v1(1989.85,1735.15) ; v1(2475.15,1479.85) ccw(c2480.06,1474.94) 2473.12,1474.94 2473.12,1474.06 cw(c2464.05,1474.06) 2470.46,1467.65 2466.23,1463.42 ccw(c2482.86,1446.78) 2459.34,1446.78 2459.34,1442.48 cw(c2448.58,1442.48) 2456.19,1434.87 2455.93,1434.87 2455.31,1434.25 ccw(c2456.82,1432.74) 2454.68,1432.74 U17.7@2454.68,1426.44 2454.68,1421.02 ccw(c2458.95,1421.02) 2455.93,1418 2456.19,1418 2457.76,1416.43 cw(c2453.96,1412.63) 2459.34,1412.63 2459.34,1409.6 cw(c2448.58,1409.6) 2456.19,1402 2455.93,1402 2455.31,1401.37 ccw(c2456.82,1399.87) 2454.68,1399.87 U17.4@2454.68,1393.56 2454.68,1387.26 ccw(c2456.82,1387.26) 2455.31,1385.75 2455.93,1385.13 2456.19,1385.13 cw(c2448.58,1377.52) 2459.34,1377.52 2459.34,1374.99 ccw(c2469.69,1374.99) 2462.37,1367.67 2465.15,1364.89 ccw(c2489.94,1389.68) 2489.94,1354.62 2569.77,1354.62 ; J2.26@2537,1000 cw(c2516.7,979.7) 2545.41,979.7 2545.41,971.08 ccw(c2561.08,971.08) 2550,960 ccw(c2550,1044.5) 2609.75,984.75 2610,985 ccw(c2573.79,1021.21) 2625,1021.21 2625,1291.72 ccw(c2546.54,1291.72) 2624.97,1293.8 ccw(c2557.07,1291.86) 2604.94,1340.06 ccw(c2569.84,1305.03) 2569.81,1354.62
  L06-BOT w5.38: v1(1989.85,1735.15) ccw(c1984.94,1740.06) 1991.88,1740.06 cw(c2003.08,1740.06) 1995.16,1747.97 cw(c2024.2,1718.94) 2024.2,1760 2058.79,1760 cw(c2058.79,1708.79) 2094.99,1745.01 2140.91,1699.09 cw(c2074.03,1632.11) 2168.68,1632.11 2168.68,1627.64 2169.67,1623.46 ccw(c2205.62,1631.94) 2174.21,1612.5 2176.46,1608.86 2179.93,1605.39 2222.66,1562.66 ccw(c2254.14,1594.14) 2254.14,1549.62 2444.77,1549.62 2444.84,1549.62 cw(c2444.84,1500.03) 2479.91,1535.09 2479.98,1535.02 2487.93,1527.07 cw(c2470.86,1510) 2495,1510 2495,1499.48 cw(c2477.41,1499.48) 2489.85,1487.03 2487.35,1484.54 cw(c2480.94,1490.95) 2480.94,1481.88 2480.06,1481.88 ccw(c2480.06,1474.94) v1(2475.15,1479.85)
P3V3: C1.1 C2.2 C3.1 C7.1 C8.2 C9.1 C13.1 C14.1 C16.1 C20.1 C21.1 C22.1 C30.1 C46.1 C47.1 C50.2 C52.1 C53.1 C54.1 C55.2 C60.1 C70.1 C71.2 C72.1 C98.1 C99.2 C100.1 C165.1 C166.2 C167.1 C188.2 C190.2 C192.2 C194.2 C196.2 C198.2 C200.2 C202.2 C204.2 C206.2 C208.2 C210.1 C212.1 C213.1 D6.2 FB1.1 FB2.1 FB7.1 J1.28 J1.29 J1.32 J1.33 J2.28 J2.29 J2.32 J2.33 J3.14 J3.16 J17.14 J17.16 L1.1 L2.1 L9.2 R1.1 R2.1 R3.1 R4.1 R5.1 R6.1 R7.1 R28.2 R41.2 R61.1 R69.2 R71.2 R74.1 R82.2 R85.2 R88.1 R90.2 R91.1 R94.1 R97.2 R98.2 R99.2 R100.2 R101.2 R102.2 R103.2 R104.2 R106.2 R108.2 R109.2 R110.2 R119.2 R136.2 R137.2 R139.2 R141.2 R142.2 R143.2 R144.2 R145.2 U3.5 U8.6 U9.5 U18.7 U18.14 U18.23 U18.33 U18.39 U18.43 U18.47 U18.53 U20.14 U22.8 | length 9872.7
  L01-TOP w7.27: U9.5@79.41,2270.35 78.78,2270.98 78.78,2297.33 v1(78.16,2297.96) 79.45,2299.25 79.45,2323.71 C60.1@80.75,2325 ; C188.2@103.17,1378.14 103.7,1377.61 103.7,1347.72 v1(104.23,1347.19) ; C50.2@133.46,2510 133.46,2578.94 D6.2@135,2580.47 ; L9.2@240,2510.68 326.43,2510.68 348.03,2532.28 R61.1@350,2532.28 ; v1(287.97,2020.11) 290.21,2017.87 U20.14@317.76,2017.87 ; R82.2@448.27,2685 449.25,2685 457.43,2676.82 457.43,2602.57 v1(475,2585) ; v1(637.36,2651.81) 637.36,2652.06 653.17,2667.87 U18.7@750.16,2667.87 ; v1(715,2545) 727.64,2557.64 U18.14@750.16,2557.64 ; v1(829.71,2828.57) 829.79,2828.48 829.79,2794.93 U18.53@829.88,2794.84 ; U18.23@908.62,2525.16 908.67,2525.11 v1(908.71,2502.67) v1(908.71,2502.67) ; U18.47@924.37,2794.84 924.43,2794.9 924.43,2837.8 v1(924.49,2837.86) ; U18.43@987.36,2794.84 987.36,2827.36 995,2835 v1(1050,2835) ; U18.33@1019.84,2620.63 1036.34,2620.63 1038.11,2622.4 1060.23,2622.4 1062.64,2620 v1(1065,2620) ; U18.39@1019.84,2715.12 1040.35,2715.12 1043.56,2718.33 1058.33,2718.33 v1(1060,2720) ; R104.2@1080.37,1783.55 1112.87,1783.55 1124.55,1771.86 v1(1126.92,1771.86) ; R88.1@2186.3,1540 2187.28,1540 2196.44,1530.84 2196.44,1512.59 v1(2222.1,1486.93) ; R85.2@2295,1508.27 2295,1467.48 v1(2295.99,1466.49) ; v1(2334.41,1461.07) 2335,1461.66 R90.2@2335,1508.27 ; R106.2@2543.19,1585.61 2543.19,1586.6 2564.36,1607.77 2570.58,1607.77 v1(2572.25,1609.44) ; R28.2@4329.69,495 4329.69,466.79 v1(4333.64,462.83)
  L01-TOP w15: v1(527.99,2840) 528.18,2839.81 528.18,2829.53 555,2802.72 R74.1@555,2801.73 ; FB7.1@3961.62,315 3963.31,313.31 3963.31,261.08 C100.1@3965,259.39
  L01-TOP w20: 2835.31,1768.55 2936.45,1768.55 2970,1735 2970,1634.91 2928,1592.91 2928,1513 2915,1500 2915,1420 v1(2905,1410) ; U3.5@4286.07,701.99 4338.01,701.99 v1(4340,700)
  L04-SIG w15: 4135.18,2732.5 4167.68,2700 4315,2700 4331.67,2716.67 4382.02,2716.67 4431.72,2666.97 v1(4431.72,2495)
  L04-SIG w20: v1(2334.41,1461.07) 2328.99,1466.49 v1(2295.99,1466.49) 2242.54,1466.49 v1(2222.1,1486.93) 2252.34,1517.17 2387.17,1517.17 2405,1535 2455,1535 2485,1565 2527.81,1565 v1(2572.25,1609.44) 2590.56,1609.44 2705,1495 2705,1455 2750,1410 2750,1325 ; v1(2905,1410) 2927.8,1387.2 2927.8,1317.8 ; 3195,2785 3195,2372.2 v1(3226.61,2340.59)
  L04-SIG w30: 109.88,2453.29 109.88,2859.71 56.26,2913.34 56.26,3195.9 130,3269.64 130,3370 122.91,3377.09 122.91,3499.89 180,3556.97 180,3590 345.08,3755.08 569.98,3755.08 585.06,3740 J17.14@684,3740
  L06-BOT w4.5: R109.2@657.31,2682.76 674.37,2699.81 674.37,2760.4 678.26,2764.3 678.26,2764.38 687.2,2773.31 R145.2@687.28,2773.31
  L06-BOT w7: R2.1@515,1183.27 R3.1@595,1183.27 750,1183.27 R7.1@755,1188.27 778.27,1188.27 800,1210 v1(800,1220)
  L06-BOT w7.27: v1(104.23,1347.19) 105,1347.97 U22.8@105,1407.28 ; v1(146.03,2354.11) 146.03,2249.24 192.6,2202.68 R69.2@192.6,2201.69 194.29,2200 R71.2@270,2200 ; R137.2@155,1272.2 155,1237.99 v1(155.71,1237.28) ; R136.2@205,1807.8 205,1859.21 v1(224.46,1878.67) ; v1(612.5,2910) 614.86,2910 625.69,2899.17 R142.2@651.37,2899.17 657.23,2905.03 R144.2@712.21,2905.03 ; J1.33@1575,1150 1613.27,1188.27 R103.2@1613.27,1240 ; J1.29@1614,171 1614,114.27 1624.11,104.16 1624.11,103.18 1632.28,95 R97.2@1633.27,95 ; R100.2@2186.73,1220 2186.73,1187.27 J2.32@2224,1150 ; J2.33@2454,1150 2488.27,1184.27 R98.2@2488.27,1225 ; J2.29@2493,171 2493,124.28 2512.28,105 R102.2@2513.27,105 ; R108.2@3000,195.24 2964.24,195.24 J3.16@2929,160 2940.92,160 2969.19,131.73 R101.2@3015,131.73 ; R119.2@3195,2341.73 3225.47,2341.73 v1(3226.61,2340.59) ; R99.2@3440,90 3482.55,90 3512.55,60 J3.14@3521,60 ; R41.2@4406.73,2525 4406.73,2503.27 4413.33,2496.67 4430.05,2496.67 v1(4431.72,2495)
  L06-BOT w10: R143.2@635,2522.8 669.72,2522.8 R110.2@689.53,2542.62 690.77,2543.85 713.85,2543.85 v1(715,2545) ; C198.2@739.25,2525 739.25,2526.97 736.38,2529.84 730.16,2529.84 v1(715,2545) ; C190.2@740.32,2561.57 740.32,2559.61 737.44,2556.73 728.36,2556.73 716.62,2545 v1(715,2545)
  L06-BOT w15: v1(287.97,2020.11) 288.24,2020.11 290.48,2017.87 C30.1@317.76,2017.87 ; C212.1@587.52,2637.85 592.25,2642.58 627.86,2642.58 637.36,2652.08 637.36,2652.27 637.17,2652.27 637.17,2652.56 613.25,2676.48 611.75,2676.48 611.38,2676.85 C196.2@611.38,2678.82 ; C196.2@611.38,2680.79 611.75,2681.16 613.72,2681.16 615.31,2682.76 R109.2@657.31,2682.76 ; R145.2@687.37,2773.31 724.08,2736.6 730,2736.6 R141.2@733.69,2732.92 ; C213.1@832.06,2860.7 829.9,2858.54 829.9,2828.76 v1(829.71,2828.57) 829.71,2828.3 830.83,2827.17 830.83,2805.24 831.2,2804.87 C208.2@833.17,2804.87 ; C213.1@832.06,2860.72 C213.1@842.4,2871.04 ; C206.2@924.37,2810.59 924.43,2810.65 924.43,2837.8 v1(924.49,2837.86) 924.76,2837.86 925.25,2837.37 943.18,2837.37 946.98,2841.17 962.68,2841.17 C210.1@972.99,2851.49 ; C204.2@1020.75,2810 1020.75,2811.97 1043.59,2834.81 1049.81,2834.81 v1(1050,2835) 1050.19,2834.81 1069.44,2834.81 1071.91,2832.34 1073.88,2832.34 1074.25,2831.97 C194.2@1074.25,2830 ; C192.2@1021.55,2777.63 1021.55,2752.78 1029.68,2744.64 1029.68,2740.71 1050.2,2720.19 1059.81,2720.19 v1(1060,2720) ; C200.2@1031.57,2634.22 1031.57,2632.25 1031.95,2631.88 1052.85,2631.88 1064.73,2620 v1(1065,2620)
  L06-BOT w20: v1(450,1860) R139.2@450,1902.2
  L06-BOT w30: 185,2430 185,2485 242.28,2542.28 480.34,2542.28 524.25,2586.2 524.25,2746.79 530.78,2753.32 530.78,2837.21 520.96,2847.03 520.96,3186.36 553,3218.4 553,3241.6 536.6,3258 534.1,3258 520.96,3271.14 ; J17.14@684,3740 905,3740 1005,3640 J17.16@1276,3640
  other v1: 4135,325 4120,350 4139.73,474.84 4140,500 779.26,1434.82 778.88,1457.92 1145,1525 171.18,2357.02 195,2360 1575,3165 1600,3165
P3V3_CM4: D1.2 D2.2 J15.84 J15.86 | length 3476.3
  L01-TOP w6: v1(3914.49,92.06) 3951.94,92.06 D2.2@3954.25,94.37 ; D1.2@4173.31,94.37 4173.31,134.43 v1(4176.15,137.27) ; J15.86@4256.35,2862.05 J15.86@4256.64,2862.34 4225.34,2862.34 4219.91,2856.91 4219.91,2850.11 4223.43,2846.59 J15.84@4256.64,2846.59
  L03-SIG w20: v1(4176.15,137.27) 4130.94,92.06 v1(3914.49,92.06) 3914.49,176.96 3928,190.47 3928,251.18 4085,408.18 4085,875 4045,915 4045,1760 4030,1775 4030,1975 4055,2000 4055,2845 4095,2885 4176.26,2885 v1(4199.04,2862.22)
P3V3_PGOOD: R56.1 U7.13 | length 228.4
  L01-TOP w7.27: U7.13@258.47,2708.58 258.47,2686.53 285,2660 335,2660 v1(340,2655)
  L06-BOT w7.27: R56.1@255,2718.27 255,2717.28 263.18,2709.11 264.16,2709.11 318.27,2655 v1(340,2655)
P4_LED0: R37.2 R53.2 R99.1 | length 1660.8
  L06-BOT w7.27: R37.2@2945,1393.27 2945,827.15 2890,772.15 2890,590.32 2955.32,525 3120,525 3330,315 3330,210 3365,175 R53.2@3440,175 R99.1@3440,123.46
P4_LED1: R38.2 R54.2 R101.1 | length 104.7
  L06-BOT w7.27: R101.1@3015,98.27 3015,97.94 3023.18,89.76 R54.2@3055,89.76 3105.74,89.76 3105.74,94.01 R38.2@3110,98.27
P4_TXRXA_N: J3.10 U1.35 U14.2 U14.9 | length 4127
  L01-TOP w5.38: U1.35@1777.18,1942.4 1809.86,1942.4 cw(c1809.86,1937.82) 1813.1,1941.06 ccw(c1816.34,1944.3) 1816.34,1939.72 1918.06,1939.72 ccw(c1918.06,1948.78) 1924.47,1942.37 1925.09,1943 cw(c1930,1938.09) v1(1930,1945.03)
  L06-BOT w5.38: v1(1930,1945.03) ccw(c1930,1938.09) 1925.1,1943 1923.59,1941.49 cw(c1919.31,1945.76) 1919.31,1939.72 cw(c1919.31,1945.09) 1915.51,1941.29 cw(c1919.31,1945.09) 1913.93,1945.09 1913.93,1948.4 cw(c1927.29,1948.4) 1917.85,1957.85 1990.72,2030.72 cw(c1994.5,2026.9) 1993.44,2032.17 cw(c1998.5,2006.5) 1998.5,2032.66 2108.36,2032.66 ccw(c2108.36,2043.04) 2115.69,2035.69 ; 2115.71,2035.71 2215,2135 cw(c2250.3,2099.7) 2250.3,2149.62 2622.8,2149.62 cw(c2622.8,2082.72) 2670.11,2130.03 cw(c2635.09,2095) 2684.62,2095 ccw(c2755.08,2095) 2705.26,2045.18 2838.55,1911.89 ccw(c2913.86,1987.2) 2913.86,1880.69 2915.34,1880.69 cw(c2915.34,1780.69) 2986.05,1851.4 2988.64,1848.81 ccw(c3041.13,1901.31) 3041.13,1827.07 3088.97,1827.07 3202.8,1827.07 cw(c3202.8,1818.92) U14.9@3208.56,1824.68 U14.2@3241.44,1824.68 3247.74,1824.68 ccw(c3247.74,1826.82) 3249.25,1825.31 3249.87,1825.93 3249.87,1826.19 cw(c3257.48,1818.58) 3257.48,1829.34 3355.38,1829.34 cw(c3355.38,1780.38) 3390,1815 3575.71,1629.29 cw(c3505,1558.58) 3604.99,1560.01 cw(c3505,1558.58) 3605,1558.58 3605,736.42 cw(c3505,736.42) 3575.71,665.71 3514.29,604.29 cw(c3443.58,675) 3443.58,575 3007.1,575 cw(c3007.1,651.71) 2952.86,597.47 2943.53,606.8 cw(c2968.58,631.85) 2933.15,631.85 2933.15,658.69 cw(c2969.12,658.69) 2943.69,684.13 2949.23,689.68 cw(c3019.94,618.96) 3019.94,718.96 3094.43,718.96 ccw(c3094.43,734.72) 3105.57,723.58 ccw(c3094.43,734.72) 3110.19,734.72 3110.19,745 3128.25,763.06 cw(c3145,746.31) J3.10@3145,770
P4_TXRXA_P: J3.11 U1.34 U14.1 U14.10 | length 4210.1
  L01-TOP w5.38: U1.34@1777.18,1926.65 1809.86,1926.65 ccw(c1809.86,1931.24) 1813.1,1928 cw(c1816.34,1924.75) 1816.34,1929.34 1918.06,1929.34 cw(c1918.06,1920.27) 1924.47,1926.68 v1@1925.09,1926.06 ; v1@1925.1,1926.05 ccw(c1930,1930.97) v1(1930,1924.03)
  L06-BOT w5.38: v1@1925.1,1926.05 ccw(c1930,1930.97) v1(1930,1924.03) ; v1@1925.09,1926.06 1924.47,1926.68 ccw(c1918.06,1920.27) 1918.06,1929.34 1917.3,1929.34 cw(c1917.3,1940.24) 1909.6,1932.52 1903.55,1938.57 1903.55,1948.4 cw(c1927.29,1948.4) 1909.83,1964.48 1910.16,1964.84 1972.66,2027.34 1983.35,2038.03 cw(c1994.5,2026.9) 1983.41,2038.08 cw(c1994.5,2026.9) 1991.35,2042.33 cw(c1998.5,2006.5) 1998.5,2043.04 2105.5,2043.04 ccw(c2105.47,2048.42) 2108.32,2043.86 ccw(c2095,2064.92) 2112.62,2047.3 2207.67,2142.35 cw(c2250.3,2099.7) 2250.3,2160 2622.96,2160 cw(c2622.96,2083.1) 2677.34,2137.48 2677.45,2137.36 cw(c2635.09,2095) 2695,2095 ccw(c2755.08,2095) 2712.6,2052.52 2845.89,1919.23 ccw(c2913.86,1987.2) 2913.86,1891.07 2915.34,1891.07 cw(c2915.34,1780.69) 2993.39,1858.74 2995.98,1856.15 ccw(c3041.13,1901.31) 3041.13,1837.45 3089.38,1837.45 3191.85,1837.45 ccw(c3191.85,1861.08) U14.10@3208.56,1844.37 U14.1@3241.44,1844.37 3247.74,1844.37 cw(c3247.74,1842.24) 3249.25,1843.75 3249.87,1843.12 3249.87,1842.87 ccw(c3257.48,1850.47) 3257.48,1839.72 3355.43,1839.72 cw(c3355.43,1780.5) 3397.31,1822.37 3584.05,1635.62 cw(c3508.43,1560) 3615.38,1560 3615.38,736.42 cw(c3505,736.42) 3583.05,658.37 3521.63,596.95 cw(c3443.58,675) 3443.58,564.62 3002.8,564.62 cw(c3002.8,641.33) 2948.56,587.09 2936.19,599.46 cw(c2968.58,631.85) 2922.77,631.85 2922.77,658.69 cw(c2969.12,658.69) 2936.35,691.47 2941.89,697.01 cw(c3019.94,618.96) 3019.94,729.34 3094.43,729.34 ccw(c3094.43,734.72) 3098.24,730.92 ccw(c3094.43,734.72) 3099.81,734.72 3099.81,738.75 ccw(c3084.71,738.75) 3095.39,749.42 3081.75,763.06 ccw(c3065,746.31) J3.11@3065,770
P4_TXRXB_N: J3.5 U1.38 U14.5 U14.6 | length 3284
  L01-TOP w5.38: U1.38@1777.18,1989.65 1809.86,1989.65 cw(c1809.86,1985.06) 1813.1,1988.3 ccw(c1816.34,1991.54) 1816.34,1986.96 2017,1986.96 ccw(c2017,1992.93) 2021.22,1988.71 ccw(c2017,1992.93) 2022.97,1992.93 2022.97,1995.09 cw(c2029.91,1995.09) v1(2025,2000)
  L06-BOT w5.38: v1(2025,2000) ccw(c2029.91,1995.09) 2022.97,1995.09 cw(c2011.77,1995.09) 2019.7,1987.19 2005.72,1973.2 2003.61,1969.46 ccw(c2030.81,1954.19) 2000.77,1962.57 1999.62,1958.49 1999.62,1945.7 2001.21,1941.71 ccw(c2022.07,1950) 2006.13,1934.2 ccw(c2029.14,1957.07) 2020.69,1925.74 2024.84,1924.62 2042.23,1924.62 2046.32,1925.94 ccw(c2037.93,1952.07) 2050.55,1927.69 2054.3,1929.62 2225.93,2101.25 cw(c2235,2092.15) 2235,2105 2616.08,2105 cw(c2616.08,2083.87) 2631.02,2098.81 2652.59,2077.24 cw(c2649.64,2074.29) 2653.81,2074.29 ccw(c2708.62,2074.29) 2669.86,2035.54 2840.94,1864.47 ccw(c2900,1923.53) 2900,1840 cw(c2900,1749.53) 2963.97,1813.5 ; 2963.94,1813.53 2979.44,1798.04 ; 2979.44,1798.03 2982.7,1795.24 ccw(c3054.45,1879.12) 3045.93,1769.08 3050.15,1768.75 3201.04,1768.75 cw(c3201.04,1758.11) U14.6@3208.56,1765.63 3214.87,1765.63 ccw(c3214.87,1767.76) 3216.37,1766.25 3217,1766.88 3217,1767.13 cw(c3224.6,1759.53) 3224.6,1770.28 3227.63,1770.28 cw(c3227.63,1764.91) 3231.43,1768.71 3233,1767.13 3233,1766.88 ccw(c3236.02,1769.89) 3236.02,1765.63 U14.5@3241.44,1765.63 3247.74,1765.63 ccw(c3247.74,1767.76) 3249.25,1766.25 3249.87,1766.88 3249.87,1767.13 cw(c3257.48,1759.53) 3257.48,1770.28 3298.3,1770.28 cw(c3298.3,1670.28) 3369.01,1740.99 3512.46,1597.54 cw(c3482.32,1567.32) 3525,1567.32 3525,1070.47 cw(c3475.58,1070.47) 3510.55,1035.55 ; J3.5@3105,670 ccw(c3105,684.16) 3115.01,674.15 3140.86,699.99 cw(c3167.61,699.99) 3148.69,718.91 3150.86,721.08 cw(c3158.2,713.74) 3158.2,724.12 ccw(c3158.2,772.76) 3192.59,738.37 3195.76,741.53 ccw(c3162.29,775) 3209.62,775 3209.62,783.58 cw(c3320,783.58) 3241.95,861.63 3308.37,928.05 cw(c3386.42,850) 3386.42,960.38 3410.46,960.38 ccw(c3410.46,1020.55) 3453,978 3510.53,1035.53
P4_TXRXB_P: J3.4 U1.37 U14.4 U14.7 | length 3283.1
  L01-TOP w5.38: U1.37@1777.18,1973.9 1809.86,1973.9 ccw(c1809.86,1978.48) 1813.1,1975.24 cw(c1816.34,1972) 1816.34,1976.58 2019.15,1976.58 ccw(c2019.15,1987.74) 2027.03,1979.84 2027.65,1980.46 cw(c2034.06,1974.05) 2034.06,1983.12 2034.94,1983.12 ccw(c2034.94,1990.06) v1(2039.85,1985.15)
  L06-BOT w5.38: v1(2039.85,1985.15) cw(c2034.94,1990.06) 2034.94,1983.12 ccw(c2034.94,1971.92) 2027.03,1979.84 2016.09,1968.91 ccw(c2030.81,1954.19) 2010,1954.19 2010,1950 ccw(c2022.07,1950) 2013.54,1941.46 ccw(c2029.14,1957.07) 2029.14,1935 2037.93,1935 ccw(c2037.93,1952.07) 2050,1940 2218.57,2108.57 cw(c2235,2092.15) 2230.2,2114.88 cw(c2235,2092.15) 2235,2115.38 2620.37,2115.38 cw(c2620.37,2094.24) 2635.32,2109.19 2659.93,2084.58 cw(c2649.64,2074.29) 2664.19,2074.29 ccw(c2708.62,2074.29) 2677.2,2042.88 2848.27,1871.8 ccw(c2900,1923.53) 2900,1850.38 cw(c2900,1749.53) 2971.31,1820.84 2983.74,1808.41 ccw(c3054.45,1879.12) 3054.45,1779.12 3193.62,1779.12 ccw(c3193.62,1800.26) U14.7@3208.56,1785.31 3214.87,1785.31 cw(c3214.87,1783.18) 3216.37,1784.69 3217,1784.07 3217,1783.81 ccw(c3224.6,1791.42) 3224.6,1780.66 3227.63,1780.66 ccw(c3227.63,1786.04) 3231.43,1782.24 3233,1783.81 3233,1784.07 cw(c3236.02,1781.05) 3236.02,1785.32 U14.4@3241.44,1785.31 3247.74,1785.31 cw(c3247.74,1783.18) 3249.25,1784.69 3249.87,1784.07 3249.87,1783.81 ccw(c3257.48,1791.42) 3257.48,1780.66 3298.4,1780.66 cw(c3298.4,1670.53) 3376.27,1748.4 3519.84,1604.84 cw(c3482.32,1567.32) 3535.38,1567.32 3535.38,1560 3535.38,1485.21 3535.38,1479.01 3535.38,1093.52 3535.38,1070.47 ; J3.4@3185,670 cw(c3185,679.1) 3178.56,672.67 3151.24,699.99 cw(c3167.61,699.99) 3156.03,711.57 3158.2,713.74 ccw(c3158.2,772.76) 3199.93,731.03 3203.1,734.2 ccw(c3162.29,775) 3220,775 3220,783.58 cw(c3320,783.58) 3249.29,854.29 3315.71,920.71 cw(c3386.42,850) 3386.42,950 3410.46,950 ccw(c3410.46,1020.55) 3460.33,970.65 ; 3460.35,970.67 3506.12,1016.44 3517.83,1028.16 ccw(c3475.58,1070.47) 3517.89,1028.22 ccw(c3475.58,1070.47) 3535.38,1070.43
P4_TXRXC_N: J3.2 U1.40 U16.2 U16.9 | length 4003.4
  L01-TOP w5.38: U1.40@1777.18,2021.14 1809.86,2021.14 cw(c1809.86,2016.56) 1813.1,2019.8 ccw(c1816.34,2023.04) 1816.34,2018.46 1954.2,2018.46 ccw(c1954.2,2040.8) 1970,2025 2017.92,2072.92 cw(c2048.75,2042.08) 2048.75,2085.69 2063.06,2085.69 ccw(c2063.06,2094.76) 2069.47,2088.34 2070.09,2088.97 cw(c2075,2084.06) v1(2075,2091) ; v1(2830,1495) ccw(c2836.94,1495) 2832.03,1490.1 2832.66,1489.47 cw(c2826.24,1483.06) 2835.31,1483.06 2835.31,1471.14 cw(c2824.41,1471.14) 2832.12,1463.43 ccw(c2839.59,1455.96) 2829.02,1455.96 cw(c2818.46,1455.96) 2825.93,1448.49 2825.87,1448.43 2825.62,1448.43 2824.99,1447.81 ccw(c2826.5,1446.3) 2824.37,1446.3 U16.2@2824.37,1440 2824.37,1433.7 ccw(c2826.5,1433.7) 2824.99,1432.19 2825.62,1431.57 2825.87,1431.57 cw(c2818.27,1423.96) 2829.02,1423.96 2829.02,1420.94 cw(c2823.65,1420.94) 2827.45,1417.13 2825.87,1415.56 2825.62,1415.56 ccw(c2828.63,1412.55) 2824.37,1412.55 U16.9@2824.37,1407.13 2824.37,1400.82 ccw(c2826.5,1400.82) 2824.99,1399.32 2825.62,1398.69 2825.87,1398.69 cw(c2818.27,1391.09) 2829.02,1391.09 2829.02,767.02 ccw(c2939.4,767.02) 2861.35,688.97 2968.37,581.95 ccw(c3046.42,660) 3046.42,549.62 3248.79,549.62 ccw(c3248.79,611.21) 3292.34,567.66 ccw(c3249.13,610.87) 3310.24,610.87 3310.24,643.32 3331.2,664.28 cw(c3345,650.48) J3.2@3345,670
  L06-BOT w5.38: v1(2075,2091) 2062.2,2085.7 2061.13,2085.7 cw(c2062.09,2156.64) 2011.84,2106.56 1974.57,2143.82 ccw(c1903.52,2072.77) 1903.52,2173.25 1792.36,2173.25 ccw(c1792.36,2144.63) 1772.12,2164.87 1761.92,2154.66 ccw(c1839.89,2076.69) 1729.62,2076.69 1729.62,1899.37 ccw(c1786.76,1899.37) 1746.35,1858.98 1752.54,1852.78 1761.83,1843.5 ccw(c1806.49,1888.17) 1806.49,1825 1996.42,1825 ccw(c1996.42,1894.01) 2045.19,1845.19 ccw(c1996.42,1894.01) 2045.23,1845.23 2213.35,2013.35 ; 2213.36,2013.36 cw(c2253.55,1973.14) 2253.55,2030 2604.05,2030 cw(c2604.05,1968.14) 2614.57,2029.1 cw(c2613.58,2023.81) 2617.36,2027.64 2806.07,1838.93 cw(c2735.31,1768.27) 2835.31,1768.27 2835.31,1512.49 v1(2830,1495)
